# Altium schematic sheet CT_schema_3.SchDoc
size 376 x 215 mm
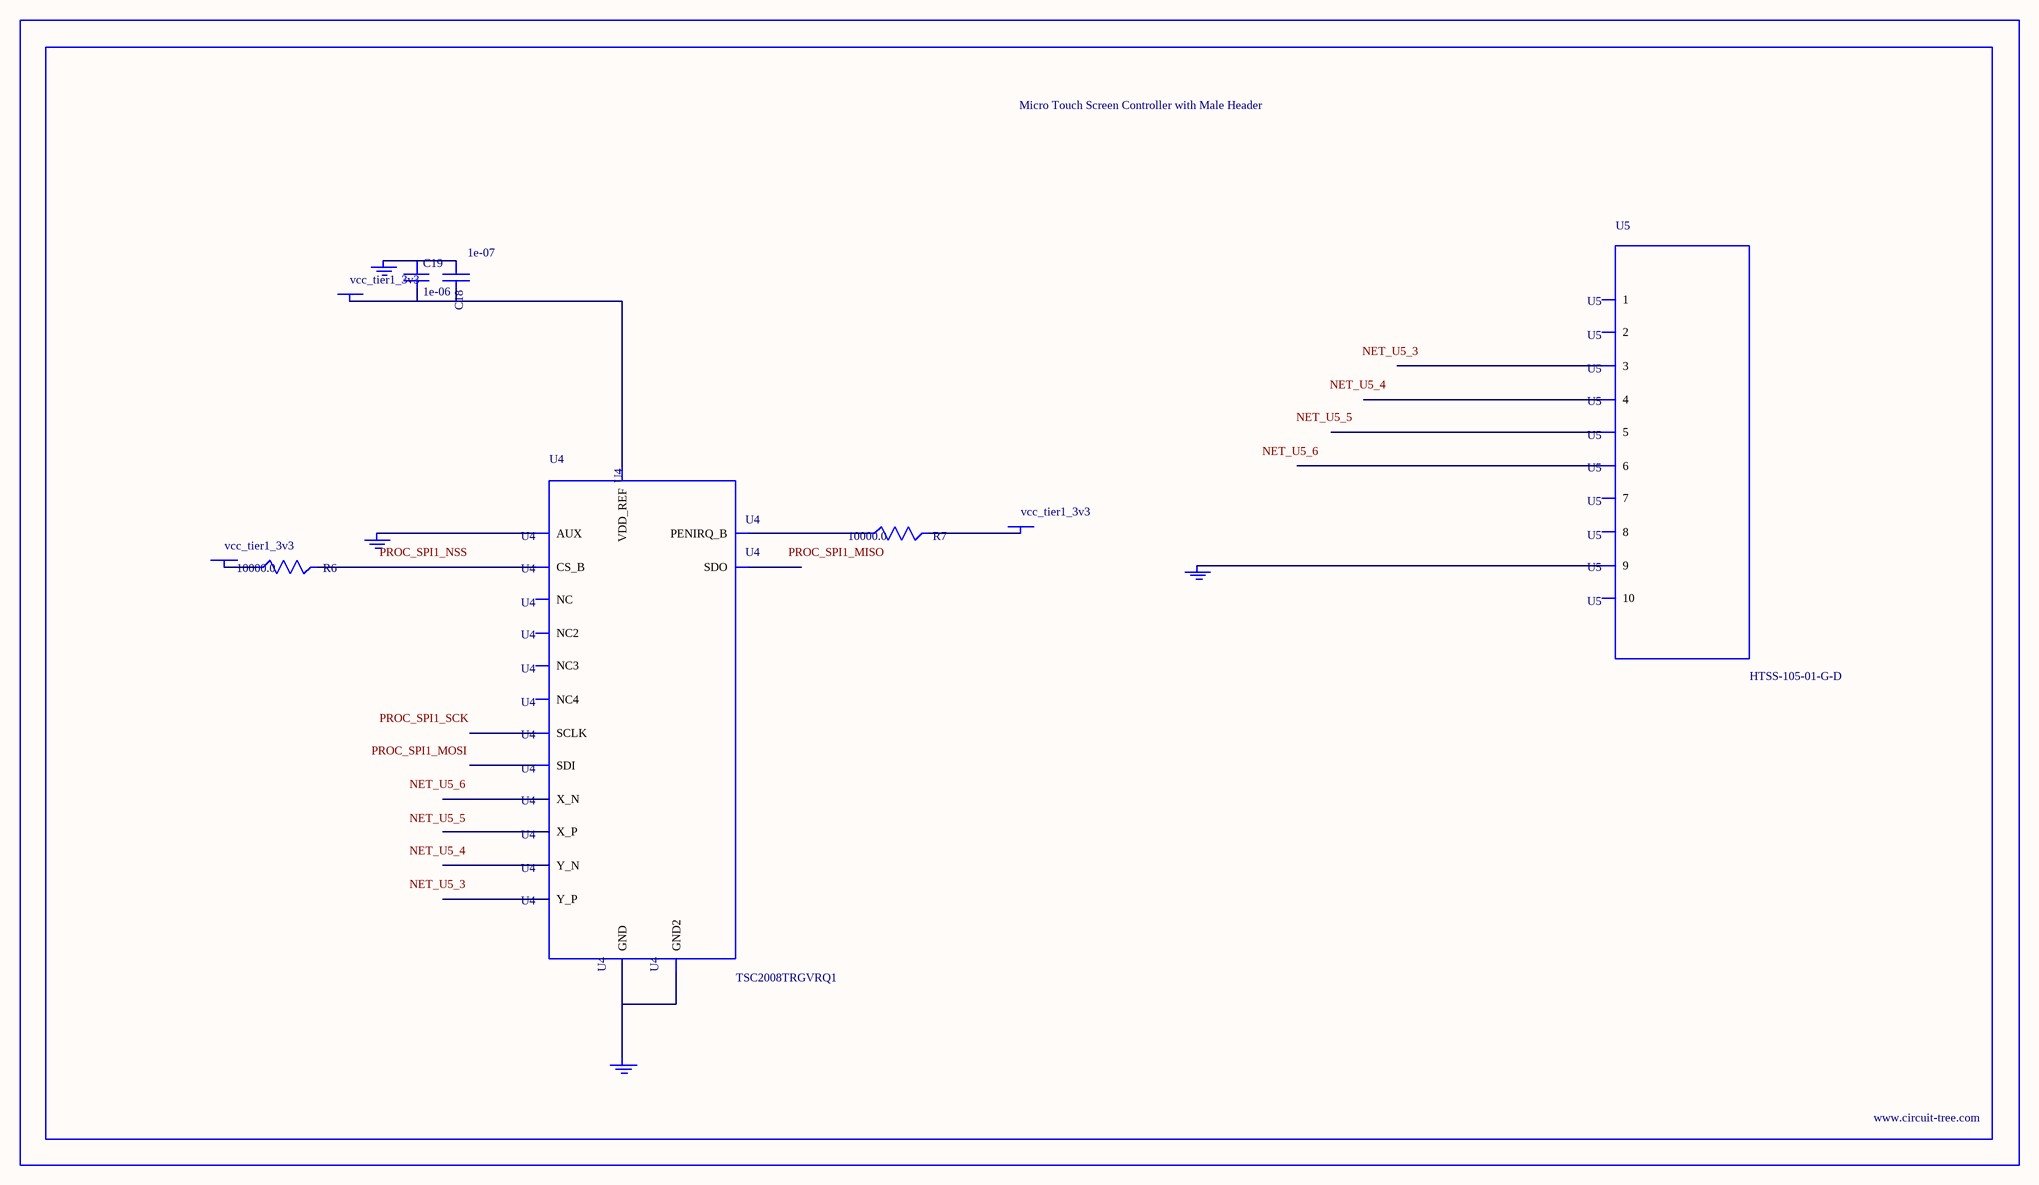
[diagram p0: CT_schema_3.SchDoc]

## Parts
BORDER2  (no value)
C18  1e-07  [C0402]
C19  1e-06  [C0603]
GND_INSTANCE_2_0  (no value)
GND_INSTANCE_2_1  (no value)
GND_INSTANCE_2_2  (no value)
GND_INSTANCE_2_3  (no value)
POWER_INSTANCE_2_0  vcc_tier1_3v3
POWER_INSTANCE_2_1  vcc_tier1_3v3
POWER_INSTANCE_2_2  vcc_tier1_3v3
R6  10000.0  [R0603]
R7  10000.0  [R0603]
U4  TSC2008TRGVRQ1  [QFN65P400X400X100-17N]
U5  HTSS-105-01-G-D  [HTSS-105-01-G-D]

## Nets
NetC18_1: C18.1 C19.1 GND_INSTANCE_2_0.0(GND)
NetC18_2: C18.2 C19.2 POWER_INSTANCE_2_1.0(PWR) U4.5(VDD_REF)
NetGND_INSTANCE_2_1_0: GND_INSTANCE_2_1.0(GND) U4.12(AUX)
NetGND_INSTANCE_2_2_0: GND_INSTANCE_2_2.0(GND) U4.10(GND) U4.17(GND2)
NetGND_INSTANCE_2_3_0: GND_INSTANCE_2_3.0(GND) U5.9
NetPOWER_INSTANCE_2_0_0: POWER_INSTANCE_2_0.0(PWR) R6.1
NetPOWER_INSTANCE_2_2_0: POWER_INSTANCE_2_2.0(PWR) R7.2
NetR6_2: R6.2 U4.3(CS_B)
NetR7_1: R7.1 U4.15(PENIRQ_B)

Not connected (* = marked no-connect by the designer): U4 1(NC) 2(SDI) 4(SCLK) 6(X_P) 7(Y_P) 8(X_N) 9(Y_N) 11(NC2) 13(NC3) 14(NC4) 16(SDO); U5 1 2 3 4 5 6 7 8 10

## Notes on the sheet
- Labels drawn without touching a wire or pin: NET_U5_3, NET_U5_4, NET_U5_5, NET_U5_6, PROC_SPI1_MISO, PROC_SPI1_MOSI, PROC_SPI1_NSS, PROC_SPI1_SCK

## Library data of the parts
BORDER2 = BORDER_PAGE2
C18 = C0402C104K3RACTU
C19 = C0603C105K3RACTU
GND_INSTANCE_2_0-GND_INSTANCE_2_3 = GND
POWER_INSTANCE_2_0-POWER_INSTANCE_2_2 = PWR
R6 R7 = RC0603JR-0710KL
